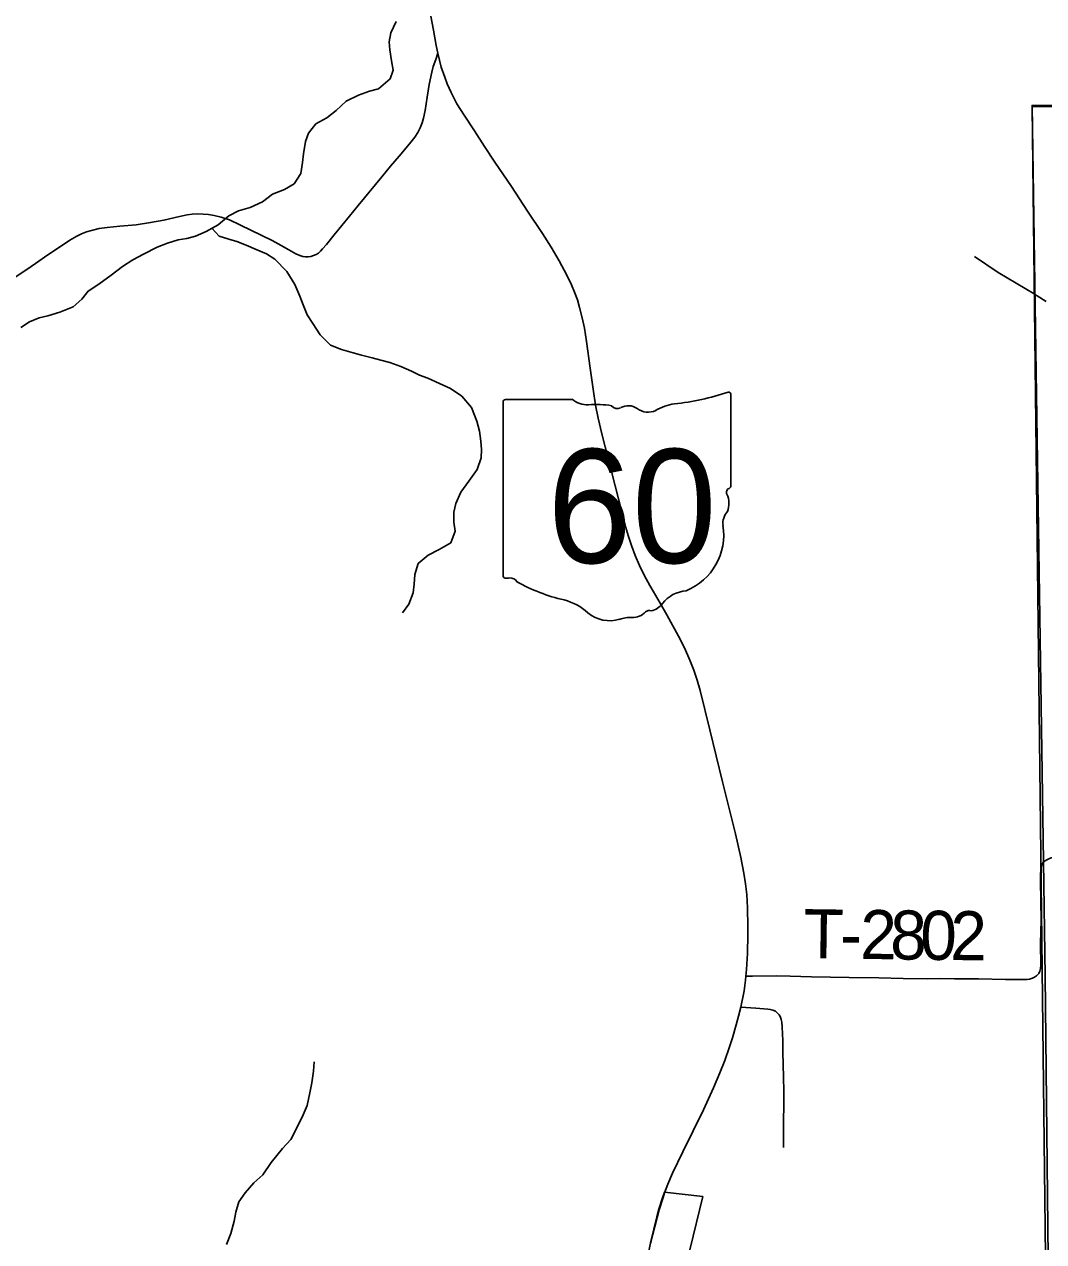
# Model space of a CAD drawing. Extents: x -7.5 to 53.5, y 0 to 22.
# Drawn here: x 3.39 to 4.57, y 17.82 to 19.229 of the extents above; entities that cross this region are included whole.
import ezdxf

# ---------------------------------------------------------------- set-up
doc = ezdxf.new("R2010")
doc.units = 0
for name, color, linetype in [('GM_X_Corporation', 7, 'Continuous'), ('GM_X_Minor_River', 7, 'Continuous'), ('GM_X_State_Location', 7, 'Continuous'), ('GM_X_State_Route', 7, 'Continuous'), ('GM_X_State_Shield', 7, 'Continuous'), ('GM_X_Township_Road', 7, 'Continuous'), ('GM_X_Township_Road_Text', 7, 'Continuous'), ('SH_Data', 7, 'Continuous')]:
    doc.layers.add(name, color=color, linetype=linetype)

msp = doc.modelspace()

# ---------------------------------------------------------------- linework, layer by layer
at = {"layer": 'GM_X_Corporation'}
for points in [[(4.6087, 14.5302), (4.6021, 15.6139), (4.594, 15.8096), (4.5873, 16.3533), (4.5872, 16.3635), (4.5826, 16.8462), (4.5822, 16.8992), (4.577, 17.1178), (4.5749, 17.2575), (4.5771, 17.6201), (4.5718, 18.1276), (4.5696, 18.2604), (4.5565, 19.1354), (5.0411, 19.1401), (6.0424, 19.1527), (6.0433, 19.1527), (6.5522, 19.1561), (7.544, 19.1455), (8.414, 19.1709), (8.5159, 19.1718), (8.9, 19.1887), (8.9, 20.9), (2.1, 20.9), (2.1, 14.1)], [(8.9, 14.1), (8.9, 19.1887), (8.5159, 19.1718), (8.414, 19.1709), (7.544, 19.1455), (6.5522, 19.1561), (6.0433, 19.1527), (6.0424, 19.1527), (5.0411, 19.1401), (4.5565, 19.1354), (4.5696, 18.2604), (4.5718, 18.1276), (4.5771, 17.6201), (4.5749, 17.2575), (4.577, 17.1178), (4.5822, 16.8992), (4.5826, 16.8462), (4.5872, 16.3635), (4.5873, 16.3533), (4.594, 15.8096), (4.6021, 15.6139), (4.6087, 14.5302)], [(4.1149, 17.8188), (4.1222, 17.8489), (4.1247, 17.8578), (4.1292, 17.8721), (4.131, 17.8774), (4.1753, 17.8723), (4.1153, 17.6257)]]:
    msp.add_lwpolyline(points, dxfattribs=at)
at = {"layer": 'GM_X_Minor_River'}
for points in [[(3.8205, 19.2323), (3.8145, 19.2193), (3.8127, 19.2091), (3.8131, 19.1996), (3.8154, 19.1871), (3.817, 19.1761), (3.8136, 19.1662), (3.8, 19.1544), (3.7898, 19.1517), (3.7769, 19.1471), (3.7629, 19.1402), (3.7512, 19.1295), (3.7403, 19.1211), (3.7278, 19.1139), (3.7191, 19.1032), (3.7158, 19.0937), (3.7132, 19.0793), (3.7124, 19.0691), (3.7102, 19.0565), (3.7027, 19.0447), (3.6914, 19.0379), (3.6777, 19.0325), (3.666, 19.0237), (3.6517, 19.0172), (3.638, 19.0134), (3.6271, 19.0076), (3.6146, 18.9973), (3.6006, 18.9893), (3.5885, 18.984), (3.5783, 18.9813), (3.5684, 18.9797), (3.5559, 18.9759), (3.5442, 18.9713), (3.5283, 18.9632), (3.5159, 18.9567), (3.5038, 18.9487), (3.4909, 18.9388), (3.4766, 18.9285), (3.4641, 18.9205), (3.4569, 18.911), (3.4467, 18.9022), (3.4316, 18.8961), (3.4176, 18.8918), (3.4074, 18.8895), (3.3964, 18.8849), (3.3862, 18.8781)], [(3.6073, 18.9931), (3.6158, 18.9841), (3.6268, 18.9807), (3.6363, 18.9777), (3.6469, 18.9736), (3.6587, 18.9687), (3.6705, 18.9634), (3.6803, 18.9574), (3.694, 18.943), (3.7032, 18.9282), (3.7093, 18.9146), (3.7131, 18.9044), (3.7177, 18.893), (3.7242, 18.8828), (3.7326, 18.8699), (3.7448, 18.8578), (3.7573, 18.8529), (3.771, 18.8488), (3.7805, 18.8462), (3.793, 18.8432), (3.8029, 18.8406), (3.8131, 18.8379), (3.826, 18.8331), (3.8382, 18.8278), (3.8476, 18.8233), (3.8571, 18.8195), (3.8708, 18.8135), (3.8833, 18.8075), (3.8966, 18.7988), (3.9077, 18.7856), (3.9138, 18.77), (3.9169, 18.7583), (3.9185, 18.7469), (3.9193, 18.737), (3.9189, 18.7275), (3.9144, 18.7139), (3.9046, 18.7005), (3.8956, 18.6876), (3.8896, 18.6747), (3.8874, 18.6644), (3.8874, 18.653), (3.889, 18.6424), (3.8837, 18.6291), (3.8705, 18.6215), (3.8576, 18.6146), (3.8459, 18.6051), (3.8422, 18.5925), (3.8415, 18.5811), (3.8404, 18.5713), (3.8351, 18.558), (3.828, 18.5481)], [(4.5588, 18.9173), (4.5173, 18.942), (4.4898, 18.9604)], [(4.5727, 18.9085), (4.5622, 18.915), (4.5588, 18.9173)], [(3.6242, 17.8168), (3.6294, 17.8297), (3.6331, 17.8438), (3.635, 17.8544), (3.6387, 17.8665), (3.6459, 17.8768), (3.6561, 17.8882), (3.6663, 17.8974), (3.676, 17.9118), (3.6892, 17.9282), (3.6987, 17.9385), (3.7051, 17.951), (3.7129, 17.967), (3.7175, 17.9777), (3.7208, 17.9925), (3.723, 18.0042), (3.7249, 18.0175), (3.7256, 18.0285)]]:
    msp.add_lwpolyline(points, dxfattribs=at)
at = {"layer": 'GM_X_State_Route'}
for points in [[(3.8688, 19.1958), (3.8669, 19.2046), (3.8637, 19.2224), (3.8609, 19.2386)], [(4.1143, 18.5796), (4.1077, 18.5916), (4.1022, 18.6028), (4.0973, 18.6142), (4.0929, 18.6259), (4.089, 18.6377), (4.0863, 18.6467), (4.0777, 18.6798), (4.0587, 18.7551), (4.0544, 18.7732), (4.0513, 18.7885), (4.0484, 18.8069), (4.0451, 18.8314), (4.0409, 18.8621), (4.0384, 18.8774), (4.0359, 18.8896), (4.0329, 18.9016), (4.0303, 18.9104), (4.0271, 18.9192), (4.0236, 18.9277), (4.0182, 18.9389), (4.0094, 18.9553), (4, 18.9713), (3.9899, 18.987), (3.9727, 19.0128), (3.9539, 19.0414), (3.9348, 19.0697), (3.923, 19.0878), (3.9113, 19.106), (3.8992, 19.1241), (3.8909, 19.1372), (3.8843, 19.1501), (3.8796, 19.1602), (3.8768, 19.1679), (3.8728, 19.1797), (3.8688, 19.1958)], [(4.1312, 17.8768), (4.1349, 17.8868), (4.1404, 17.8995), (4.1523, 17.9242), (4.1761, 17.9729), (4.1877, 17.9984), (4.1952, 18.0155), (4.201, 18.0299), (4.2061, 18.0445), (4.2098, 18.0563), (4.2142, 18.0712), (4.2167, 18.0811), (4.2193, 18.0915), (4.2232, 18.1107), (4.225, 18.123), (4.2254, 18.1276), (4.2262, 18.1353), (4.2272, 18.1539), (4.2276, 18.1756), (4.2276, 18.1849), (4.2272, 18.2066), (4.2263, 18.2221), (4.225, 18.2344), (4.2231, 18.2466), (4.2194, 18.2648), (4.2131, 18.2921), (4.1981, 18.3524), (4.1834, 18.4128), (4.1723, 18.458), (4.1689, 18.47), (4.165, 18.4817), (4.1605, 18.4932), (4.1542, 18.5074), (4.1472, 18.5212), (4.1337, 18.5457), (4.1261, 18.5591), (4.1152, 18.5779), (4.1143, 18.5796)], [(4.0684, 17.6236), (4.071, 17.6348), (4.0776, 17.6619), (4.0859, 17.6949), (4.0955, 17.7372), (4.1013, 17.7612), (4.1059, 17.7792), (4.1103, 17.7972), (4.1151, 17.8183), (4.1225, 17.8483), (4.1249, 17.8572), (4.1294, 17.8715), (4.1312, 17.8768)]]:
    msp.add_lwpolyline(points, dxfattribs=at)
at = {"layer": 'GM_X_State_Shield'}
for p, q in [((4.208, 18.6954), (4.208, 18.8001)), ((3.9443, 18.7917), (3.9443, 18.5916)), ((4.0241, 18.7951), (3.9469, 18.7951)), ((4.208, 18.6954), (4.208, 18.6954))]:
    msp.add_line(p, q, dxfattribs=at)
for centre, radius, start, end in [((4.1141, 19.068), 0.2796, 275.8445, 288.9065), ((4.2051, 18.8005), 0.00294, 351.8621, 97.738), ((3.9474, 18.7921), 0.00305, 98.1301, 188.1301), ((4.0425, 18.8184), 0.0296, 231.6195, 271.1119), ((4.0524, 18.6828), 0.1064, 80.4867, 94.9883), ((4.0765, 18.7931), 0.00855, 219.7921, 297.1024), ((4.0891, 18.77), 0.0178, 54.4667, 119.1411), ((4.112, 18.8017), 0.0214, 233.8562, 294.8282), ((4.1497, 18.734), 0.0563, 97.3462, 120.7689), ((4.2073, 18.6877), 0.00454, 107.944, 210.337), ((4.1784, 18.6745), 0.0273, 340.033, 23.6496), ((4.2049, 18.695), 0.00314, 289.6038, 7.7341), ((4.2185, 18.6516), 0.0198, 136.8065, 186.9296), ((4.1297, 18.6383), 0.0699, 292.3089, 8.9858), ((3.9474, 18.5911), 0.00308, 171.9584, 258.3066), ((3.9478, 18.6116), 0.0235, 267.339, 280.6039), ((3.9527, 18.58), 0.00848, 29.7484, 93.2717), ((4.0597, 18.7598), 0.2019, 240.4129, 257.1985), ((4.1592, 18.5354), 0.0383, 94.4031, 142.5768), ((3.9995, 18.5017), 0.0632, 47.1842, 75.836), ((4.1107, 18.5722), 0.0226, 282.8732, 323.2771), ((4.0679, 18.579), 0.0401, 230.7004, 286.2918), ((4.091, 18.5098), 0.0329, 85.6951, 111.2099), ((4.0939, 18.564), 0.0214, 268.777, 315.5493), ((4.1133, 18.5447), 0.00601, 65.7517, 132.6484)]:
    msp.add_arc(centre, radius, start, end, dxfattribs=at)
at = {"layer": 'GM_X_Township_Road'}
for points in [[(3.3763, 18.9343), (3.3942, 18.9463), (3.4071, 18.9549), (3.4177, 18.9625), (3.4275, 18.9691), (3.4431, 18.9792), (3.4511, 18.9839), (3.4566, 18.9866), (3.4622, 18.9889), (3.4681, 18.9907), (3.4771, 18.9927), (3.4863, 18.994), (3.5007, 18.9954), (3.5196, 18.9971), (3.5365, 18.9998), (3.5519, 19.0025), (3.57, 19.0068), (3.5788, 19.0088), (3.5847, 19.0096), (3.5911, 19.0099), (3.5973, 19.0095), (3.6036, 19.0089), (3.6101, 19.0079), (3.618, 19.006), (3.6279, 19.0028), (3.6524, 18.991), (3.677, 18.979), (3.6876, 18.9732), (3.6966, 18.968), (3.7046, 18.9637), (3.7093, 18.9616), (3.7126, 18.9606), (3.7156, 18.9602), (3.7188, 18.9601), (3.722, 18.9605), (3.725, 18.9615), (3.7279, 18.9628), (3.7306, 18.9645), (3.7331, 18.9666), (3.7353, 18.9692), (3.7399, 18.9745), (3.7487, 18.9857), (3.7665, 19.0072), (3.7766, 19.0194), (3.804, 19.0527), (3.8139, 19.0649), (3.8242, 19.0767), (3.836, 19.0909), (3.8421, 19.0987), (3.8456, 19.1041), (3.8483, 19.1093), (3.8506, 19.1153), (3.8521, 19.1205), (3.8542, 19.1295), (3.8566, 19.1447), (3.8589, 19.1597), (3.8619, 19.1738), (3.8636, 19.1802), (3.8665, 19.1886), (3.8688, 19.1958)], [(4.2254, 18.1276), (4.2328, 18.1276), (4.2609, 18.1277), (4.2764, 18.1274), (4.3013, 18.1266), (4.3232, 18.1263), (4.345, 18.126), (4.3793, 18.1254), (4.4073, 18.1249), (4.4354, 18.1246), (4.451, 18.1247), (4.4666, 18.1246), (4.4946, 18.1243), (4.5258, 18.1238), (4.5445, 18.1235), (4.5507, 18.1238), (4.5535, 18.1242), (4.5568, 18.1252), (4.5592, 18.1262), (4.5616, 18.1278), (4.5641, 18.1307), (4.5656, 18.1333), (4.5663, 18.1365), (4.5666, 18.1402), (4.5663, 18.1653), (4.5668, 18.1925), (4.5667, 18.2142), (4.5663, 18.2381), (4.5664, 18.2455), (4.5667, 18.2502), (4.5671, 18.2534), (4.5679, 18.2568), (4.5698, 18.2599)], [(4.5698, 18.2599), (4.5735, 18.2623), (4.5758, 18.2634), (4.5787, 18.2644), (4.5817, 18.265), (4.5848, 18.2653), (4.5909, 18.2655), (4.6026, 18.2654), (4.6184, 18.2653), (4.6365, 18.2651), (4.6554, 18.265), (4.6704, 18.2648), (4.6902, 18.2647), (4.7052, 18.2642), (4.7287, 18.2635), (4.7449, 18.2631), (4.7577, 18.2627), (4.7771, 18.2621), (4.7987, 18.2615), (4.8172, 18.2613), (4.8265, 18.2612), (4.8513, 18.2613), (4.8664, 18.2614)], [(4.2687, 17.9291), (4.2687, 17.94), (4.2687, 17.9461), (4.2688, 17.9523), (4.269, 17.9645), (4.2691, 17.9736), (4.2692, 17.9797), (4.2691, 17.9919), (4.2691, 17.998), (4.2689, 18.0071), (4.2689, 18.0101), (4.2685, 18.0254), (4.2682, 18.0395), (4.2679, 18.0438), (4.2679, 18.0531), (4.2672, 18.0683), (4.2668, 18.0741), (4.2663, 18.0775), (4.2654, 18.0801), (4.2638, 18.0829), (4.262, 18.0847), (4.2596, 18.0868), (4.2566, 18.0882), (4.2535, 18.0891), (4.2507, 18.0895), (4.2369, 18.0905), (4.2193, 18.0915)]]:
    msp.add_lwpolyline(points, dxfattribs=at)
at = {"layer": 'SH_Data'}
msp.add_lwpolyline([(8.9, 19.1896), (4.5566, 19.1336), (4.6149, 14.11), (4.6151, 14.1)], dxfattribs=at)

# ---------------------------------------------------------------- texts
at = {"layer": 'GM_X_State_Location'}
for s in ['s', 'r']:
    msp.add_text(s, height=0.000189, dxfattribs=at).set_placement((4.0732, 18.6783))
msp.add_text('60', height=0.000189, rotation=0, dxfattribs=at).set_placement((4.0255, 18.6645))
at = {"layer": 'GM_X_State_Shield'}
msp.add_text('60', height=0.13184, dxfattribs=at).set_placement((3.9954, 18.6057))
at = {"layer": 'GM_X_Township_Road_Text'}
for s, rotation, p in [('T', 359.1773, (4.2917, 18.1484)), ('2', 359.2713, (4.3573, 18.1475)), ('8', 359.2817, (4.392, 18.147)), ('0', 359.2928, (4.4268, 18.1466)), ('2', 359.3073, (4.4615, 18.1462)), ('-', 359.1994, (4.3341, 18.1478))]:
    msp.add_text(s, height=0.0568, rotation=rotation, dxfattribs=at).set_placement(p)

doc.saveas('drawing.dxf')
